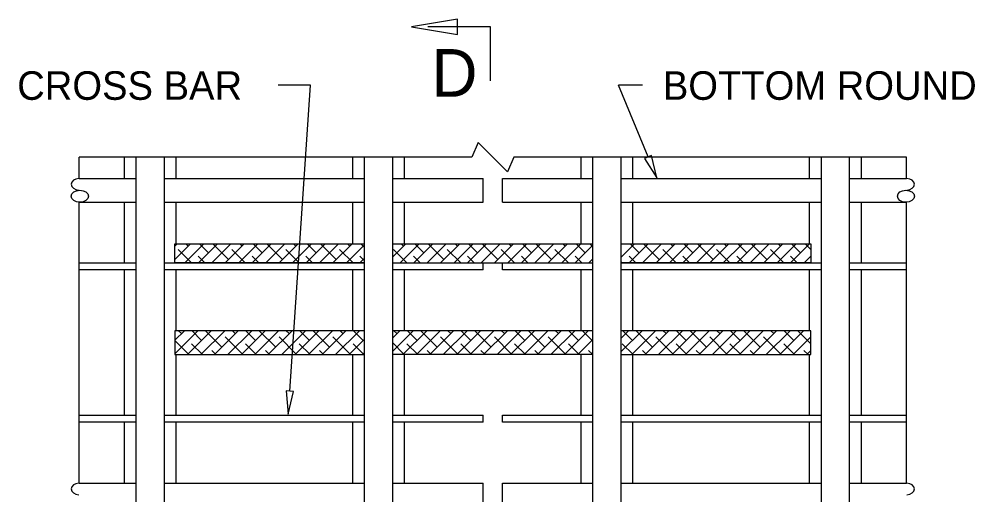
# Model space of a CAD drawing. Extents: x -24512 to -22484, y 4569 to 6351.
# Drawn here: x -24120.5 to -24020.1, y 5479 to 5529 of the extents above; entities that cross this region are included whole.
import ezdxf

# ---------------------------------------------------------------- set-up
doc = ezdxf.new("R2010")
doc.units = 0
for name, color, linetype in [('10', 7, 'Continuous'), ('3', 7, 'Continuous'), ('4', 7, 'Continuous'), ('8', 7, 'Continuous'), ('9', 7, 'Continuous')]:
    doc.layers.add(name, color=color, linetype=linetype)

# ---------------------------------------------------------------- blocks, each defined once
blk = doc.blocks.new('SYM048')
at = {"layer": '3'}
for p, q in [((150.97425, 287.263125), (151.306125, 287.595)), ((150.97425, 287.54825), (151.021, 287.595)), ((151.188, 287.19175), (151.59125, 287.595)), ((151.25775, 287.546625), (151.209375, 287.595)), ((151.473125, 287.19175), (151.876375, 287.595)), ((151.6855, 287.404), (151.4945, 287.595)), ((151.75825, 287.19175), (152.1615, 287.595)), ((152.113125, 287.2615), (151.779625, 287.595)), ((152.043375, 287.19175), (152.446625, 287.595)), ((152.3285, 287.19175), (152.73175, 287.595)), ((152.39825, 287.546625), (152.349875, 287.595)), ((152.613625, 287.19175), (153.016875, 287.595)), ((152.825875, 287.404), (152.635, 287.595)), ((152.89875, 287.19175), (153.302, 287.595)), ((153.253625, 287.2615), (152.920125, 287.595)), ((153.183875, 287.19175), (153.587125, 287.595)), ((153.469, 287.19175), (153.87225, 287.595)), ((153.53875, 287.546625), (153.490375, 287.595)), ((153.754125, 287.19175), (154.157375, 287.595)), ((153.966375, 287.404), (153.7755, 287.595)), ((154.03925, 287.19175), (154.4425, 287.595)), ((154.394125, 287.2615), (154.060625, 287.595)), ((154.324375, 287.19175), (154.727625, 287.595)), ((154.6095, 287.19175), (154.991375, 287.573625)), ((154.67925, 287.546625), (154.630875, 287.595)), ((154.991375, 287.519625), (154.916, 287.595)), ((151.3275, 287.19175), (151.043875, 287.475375)), ((151.612625, 287.19175), (151.471625, 287.33275)), ((152.468, 287.19175), (152.184375, 287.475375)), ((152.753125, 287.19175), (152.612125, 287.33275)), ((153.6085, 287.19175), (153.324875, 287.475375)), ((153.893625, 287.19175), (153.752625, 287.33275)), ((154.749, 287.19175), (154.465375, 287.475375)), ((154.991375, 287.2345), (154.893125, 287.33275)), ((154.894625, 287.19175), (154.991375, 287.2885))]:
    blk.add_line(p, q, dxfattribs=at)
blk = doc.blocks.new('SYM049')
at = {"layer": '3'}
for p, q in [((155.5905, 287.317375), (155.868125, 287.595)), ((155.75, 287.19175), (156.15325, 287.595)), ((155.81975, 287.546625), (155.771375, 287.595)), ((156.035125, 287.19175), (156.438375, 287.595)), ((156.247375, 287.404), (156.0565, 287.595)), ((156.32025, 287.19175), (156.7235, 287.595)), ((156.675125, 287.2615), (156.341625, 287.595)), ((156.605375, 287.19175), (157.0085, 287.595)), ((156.8905, 287.19175), (157.293625, 287.595)), ((156.96025, 287.546625), (156.911875, 287.595)), ((157.175625, 287.19175), (157.57875, 287.595)), ((157.387875, 287.404), (157.197, 287.595)), ((157.46075, 287.19175), (157.863875, 287.595)), ((157.815625, 287.2615), (157.482125, 287.595)), ((157.745875, 287.19175), (158.149, 287.595)), ((158.031, 287.19175), (158.434125, 287.595)), ((158.10075, 287.546625), (158.052375, 287.595)), ((158.316125, 287.19175), (158.71925, 287.595)), ((158.528375, 287.404), (158.3375, 287.595)), ((158.60125, 287.19175), (159.004375, 287.595)), ((158.956125, 287.2615), (158.622625, 287.595)), ((158.886375, 287.19175), (159.2895, 287.595)), ((159.1715, 287.19175), (159.574625, 287.595)), ((159.24125, 287.546625), (159.192875, 287.595)), ((159.456625, 287.19175), (159.83, 287.56525)), ((159.668875, 287.404), (159.478, 287.595)), ((159.83, 287.528), (159.763125, 287.595)), ((155.8895, 287.19175), (155.605875, 287.475375)), ((156.174625, 287.19175), (156.033625, 287.33275)), ((157.03, 287.19175), (156.746375, 287.475375)), ((157.315125, 287.19175), (157.174125, 287.33275)), ((158.1705, 287.19175), (157.886875, 287.475375)), ((158.455625, 287.19175), (158.3145, 287.33275)), ((159.311, 287.19175), (159.027375, 287.475375)), ((159.596125, 287.19175), (159.455, 287.33275)), ((159.74175, 287.19175), (159.83, 287.280125))]:
    blk.add_line(p, q, dxfattribs=at)
blk = doc.blocks.new('SYM050')
at = {"layer": '3'}
for p, q in [((160.42925, 287.309), (160.715125, 287.595)), ((160.42925, 287.594125), (160.43, 287.595)), ((160.597, 287.19175), (161.00025, 287.595)), ((160.809375, 287.404), (160.6185, 287.595)), ((160.882125, 287.19175), (161.285375, 287.595)), ((161.237125, 287.2615), (160.903625, 287.595)), ((161.16725, 287.19175), (161.5705, 287.595)), ((161.452375, 287.19175), (161.855625, 287.595)), ((161.52225, 287.546625), (161.473875, 287.595)), ((161.7375, 287.19175), (162.14075, 287.595)), ((161.949875, 287.404), (161.759, 287.595)), ((162.022625, 287.19175), (162.425875, 287.595)), ((162.3775, 287.2615), (162.044125, 287.595)), ((162.30775, 287.19175), (162.711, 287.595)), ((162.592875, 287.19175), (162.996125, 287.595)), ((162.662625, 287.546625), (162.614375, 287.595)), ((162.878, 287.19175), (163.28125, 287.595)), ((163.090375, 287.404), (162.8995, 287.595)), ((163.163125, 287.19175), (163.566375, 287.595)), ((163.518, 287.2615), (163.184625, 287.595)), ((163.44825, 287.19175), (163.8515, 287.595)), ((163.733375, 287.19175), (164.136625, 287.595)), ((163.803125, 287.546625), (163.754875, 287.595)), ((164.0185, 287.19175), (164.42175, 287.595)), ((164.230875, 287.404), (164.04, 287.595)), ((164.446375, 287.473625), (164.325125, 287.595)), ((160.736625, 287.19175), (160.5955, 287.33275)), ((161.592, 287.19175), (161.308375, 287.475375)), ((161.877125, 287.19175), (161.736, 287.33275)), ((162.7325, 287.19175), (162.448875, 287.475375)), ((163.017625, 287.19175), (162.8765, 287.33275)), ((163.873, 287.19175), (163.589375, 287.475375)), ((164.158, 287.19175), (164.017, 287.33275)), ((164.303625, 287.19175), (164.446375, 287.334375)), ((160.4515, 287.19175), (160.42925, 287.214))]:
    blk.add_line(p, q, dxfattribs=at)
blk = doc.blocks.new('SYM051')
at = {"layer": '3'}
for p, q in [((150.97425, 285.26725), (151.46225, 285.75525)), ((150.97425, 285.552375), (151.177125, 285.75525)), ((151.11525, 285.693375), (151.05325, 285.75525)), ((151.243375, 285.25125), (151.747375, 285.75525)), ((151.542875, 285.55075), (151.338375, 285.75525)), ((151.5285, 285.25125), (152.0325, 285.75525)), ((151.970625, 285.40825), (151.6235, 285.75525)), ((151.813625, 285.25125), (152.317625, 285.75525)), ((152.09875, 285.25125), (152.60275, 285.75525)), ((152.25575, 285.693375), (152.19375, 285.75525)), ((152.383875, 285.25125), (152.887875, 285.75525)), ((152.683375, 285.55075), (152.478875, 285.75525)), ((152.669, 285.25125), (153.173, 285.75525)), ((153.111, 285.40825), (152.764, 285.75525)), ((152.954125, 285.25125), (153.458125, 285.75525)), ((153.23925, 285.25125), (153.74325, 285.75525)), ((153.396125, 285.693375), (153.33425, 285.75525)), ((153.524375, 285.25125), (154.028375, 285.75525)), ((153.823875, 285.55075), (153.619375, 285.75525)), ((153.8095, 285.25125), (154.3135, 285.75525)), ((154.2515, 285.40825), (153.9045, 285.75525)), ((154.094625, 285.25125), (154.598625, 285.75525)), ((154.37975, 285.25125), (154.88375, 285.75525)), ((154.536625, 285.693375), (154.47475, 285.75525)), ((154.964375, 285.55075), (154.759875, 285.75525)), ((151.25775, 285.265625), (150.97425, 285.549125)), ((151.55725, 285.25125), (151.329, 285.4795)), ((152.39825, 285.265625), (152.041875, 285.622)), ((152.69775, 285.25125), (152.4695, 285.4795)), ((153.53875, 285.265625), (153.182375, 285.622)), ((153.83825, 285.25125), (153.61, 285.4795)), ((154.67925, 285.265625), (154.322875, 285.622)), ((154.664875, 285.25125), (154.991375, 285.57775)), ((154.97875, 285.25125), (154.7505, 285.4795)), ((151.842375, 285.25125), (151.75675, 285.336875)), ((152.982875, 285.25125), (152.89725, 285.336875)), ((154.123375, 285.25125), (154.03775, 285.336875)), ((154.95, 285.25125), (154.991375, 285.292625))]:
    blk.add_line(p, q, dxfattribs=at)
blk = doc.blocks.new('SYM052')
at = {"layer": '3'}
for p, q in [((155.5905, 285.321625), (156.02425, 285.75525)), ((155.5905, 285.606625), (155.739125, 285.75525)), ((155.677125, 285.693375), (155.61525, 285.75525)), ((155.80525, 285.25125), (156.309375, 285.75525)), ((156.104875, 285.55075), (155.900375, 285.75525)), ((156.090375, 285.25125), (156.5945, 285.75525)), ((156.5325, 285.40825), (156.1855, 285.75525)), ((156.3755, 285.25125), (156.879625, 285.75525)), ((156.660625, 285.25125), (157.16475, 285.75525)), ((156.817625, 285.693375), (156.75575, 285.75525)), ((156.94575, 285.25125), (157.449875, 285.75525)), ((157.245375, 285.55075), (157.040875, 285.75525)), ((157.230875, 285.25125), (157.735, 285.75525)), ((157.673, 285.40825), (157.326, 285.75525)), ((157.516, 285.25125), (158.020125, 285.75525)), ((157.801125, 285.25125), (158.30525, 285.75525)), ((157.958125, 285.693375), (157.89625, 285.75525)), ((158.08625, 285.25125), (158.590375, 285.75525)), ((158.385875, 285.55075), (158.181375, 285.75525)), ((158.371375, 285.25125), (158.8755, 285.75525)), ((158.8135, 285.40825), (158.4665, 285.75525)), ((158.6565, 285.25125), (159.160625, 285.75525)), ((158.941625, 285.25125), (159.44575, 285.75525)), ((159.098625, 285.693375), (159.03675, 285.75525)), ((159.22675, 285.25125), (159.730875, 285.75525)), ((159.526375, 285.55075), (159.321875, 285.75525)), ((159.83, 285.532125), (159.607, 285.75525)), ((155.81975, 285.265625), (155.5905, 285.494875)), ((156.11925, 285.25125), (155.891, 285.4795)), ((156.96025, 285.265625), (156.603875, 285.622)), ((157.25975, 285.25125), (157.0315, 285.4795)), ((158.10075, 285.265625), (157.74425, 285.622)), ((158.40025, 285.25125), (158.172, 285.4795)), ((159.24125, 285.265625), (158.88475, 285.622)), ((159.54075, 285.25125), (159.3125, 285.4795)), ((159.511875, 285.25125), (159.83, 285.569375)), ((156.404375, 285.25125), (156.31875, 285.336875)), ((157.544875, 285.25125), (157.459125, 285.336875)), ((158.685375, 285.25125), (158.599625, 285.336875)), ((159.825875, 285.25125), (159.740125, 285.336875)), ((159.797, 285.25125), (159.83, 285.28425))]:
    blk.add_line(p, q, dxfattribs=at)
blk = doc.blocks.new('SYM053')
at = {"layer": '3'}
for p, q in [((160.42925, 285.313125), (160.87125, 285.75525)), ((160.42925, 285.59825), (160.586125, 285.75525)), ((160.666875, 285.55075), (160.462375, 285.75525)), ((160.652375, 285.25125), (161.156375, 285.75525)), ((161.0945, 285.40825), (160.7475, 285.75525)), ((160.9375, 285.25125), (161.4415, 285.75525)), ((161.222625, 285.25125), (161.726625, 285.75525)), ((161.379625, 285.693375), (161.31775, 285.75525)), ((161.50775, 285.25125), (162.01175, 285.75525)), ((161.807375, 285.55075), (161.602875, 285.75525)), ((161.792875, 285.25125), (162.296875, 285.75525)), ((162.235, 285.40825), (161.888, 285.75525)), ((162.078, 285.25125), (162.582, 285.75525)), ((162.363125, 285.25125), (162.867125, 285.75525)), ((162.520125, 285.693375), (162.45825, 285.75525)), ((162.64825, 285.25125), (163.15225, 285.75525)), ((162.94775, 285.55075), (162.743375, 285.75525)), ((162.933375, 285.25125), (163.437375, 285.75525)), ((163.3755, 285.40825), (163.0285, 285.75525)), ((163.2185, 285.25125), (163.7225, 285.75525)), ((163.503625, 285.25125), (164.007625, 285.75525)), ((163.660625, 285.693375), (163.59875, 285.75525)), ((163.78875, 285.25125), (164.29275, 285.75525)), ((164.08825, 285.55075), (163.88375, 285.75525)), ((164.446375, 285.47775), (164.168875, 285.75525)), ((160.68125, 285.25125), (160.453, 285.4795)), ((161.52225, 285.265625), (161.16575, 285.622)), ((161.82175, 285.25125), (161.5935, 285.4795)), ((162.662625, 285.265625), (162.30625, 285.622)), ((162.96225, 285.25125), (162.734, 285.4795)), ((163.803125, 285.265625), (163.44675, 285.622)), ((164.10275, 285.25125), (163.8745, 285.4795)), ((164.073875, 285.25125), (164.446375, 285.62375)), ((160.966375, 285.25125), (160.880625, 285.336875)), ((162.106875, 285.25125), (162.021125, 285.336875)), ((163.247375, 285.25125), (163.161625, 285.336875)), ((164.387875, 285.25125), (164.302125, 285.336875)), ((164.359, 285.25125), (164.446375, 285.338625))]:
    blk.add_line(p, q, dxfattribs=at)

msp = doc.modelspace()

# ---------------------------------------------------------------- linework, layer by layer
at = {"layer": '10'}
for centre, major_axis, start_param, end_param in [((-24114.15, 5511.66), (0.895, 0), 1.692197, 4.591233), ((-24027.36, 5511.66), (-0.895, 0), 1.691952, 4.590988), ((-24114.15, 5479.66), (0.895, 0), 1.692197, 4.591233), ((-24027.36, 5479.66), (-0.895, 0), 1.691952, 4.590988)]:
    msp.add_ellipse(centre, major_axis=major_axis, ratio=0.699516, start_param=start_param, end_param=end_param, dxfattribs=at)
for centre, major_axis in [((-24114.15, 5510.41), (0.895, 0)), ((-24027.36, 5510.41), (-0.895, 0))]:
    msp.add_ellipse(centre, major_axis=major_axis, ratio=0.699516, dxfattribs=at)
at = {"layer": '3'}
msp.add_lwpolyline([(-24074.46, 5527.39), (-24074.46, 5529.01), (-24079.31, 5528.2)], close=True, dxfattribs=at)
msp.add_lwpolyline([(-24071, 5522.54), (-24071, 5528.2), (-24077.59, 5528.2)], dxfattribs=at)
at = {"layer": '4'}
for p, q in [((-24114.23, 5512.28), (-24114.23, 5514.51)), ((-24109.47, 5512.28), (-24109.47, 5514.51)), ((-24108.24, 5427.56), (-24108.24, 5514.51)), ((-24105.27, 5427.56), (-24105.27, 5514.51)), ((-24104.04, 5512.28), (-24104.04, 5514.51)), ((-24085.48, 5512.28), (-24085.48, 5514.51)), ((-24084.24, 5427.56), (-24084.24, 5514.51)), ((-24081.27, 5427.56), (-24081.27, 5514.51)), ((-24080.04, 5512.28), (-24080.04, 5514.51)), ((-24061.48, 5512.28), (-24061.48, 5514.51)), ((-24060.24, 5427.56), (-24060.24, 5514.51)), ((-24057.27, 5427.56), (-24057.27, 5514.51)), ((-24056.04, 5512.28), (-24056.04, 5514.51)), ((-24037.48, 5512.28), (-24037.48, 5514.51)), ((-24036.24, 5427.56), (-24036.24, 5514.51)), ((-24033.27, 5427.56), (-24033.27, 5514.51)), ((-24032.04, 5512.28), (-24032.04, 5514.51)), ((-24027.29, 5512.28), (-24027.29, 5514.51)), ((-24114.23, 5512.28), (-24108.24, 5512.28)), ((-24105.27, 5512.28), (-24084.24, 5512.28)), ((-24081.27, 5512.28), (-24071.76, 5512.28)), ((-24071.76, 5509.78), (-24071.76, 5512.28)), ((-24069.76, 5509.78), (-24069.76, 5512.28)), ((-24069.76, 5512.28), (-24060.24, 5512.28)), ((-24057.27, 5512.28), (-24036.24, 5512.28)), ((-24033.27, 5512.28), (-24027.29, 5512.28)), ((-24114.23, 5480.28), (-24114.23, 5509.78)), ((-24114.23, 5509.78), (-24108.24, 5509.78)), ((-24109.47, 5503.41), (-24109.47, 5509.78)), ((-24105.27, 5509.78), (-24084.24, 5509.78)), ((-24104.04, 5505.41), (-24104.04, 5509.78)), ((-24085.48, 5505.41), (-24085.48, 5509.78)), ((-24081.27, 5509.78), (-24071.76, 5509.78)), ((-24080.04, 5505.41), (-24080.04, 5509.78)), ((-24069.76, 5509.78), (-24060.24, 5509.78)), ((-24061.48, 5505.41), (-24061.48, 5509.78)), ((-24057.27, 5509.78), (-24036.24, 5509.78)), ((-24056.04, 5505.41), (-24056.04, 5509.78)), ((-24037.48, 5505.41), (-24037.48, 5509.78)), ((-24033.27, 5509.78), (-24027.29, 5509.78)), ((-24032.04, 5503.41), (-24032.04, 5509.78)), ((-24027.29, 5480.28), (-24027.29, 5509.78)), ((-24114.23, 5503.41), (-24108.24, 5503.41)), ((-24105.27, 5503.41), (-24084.24, 5503.41)), ((-24081.27, 5503.41), (-24071.76, 5503.41)), ((-24071.76, 5502.66), (-24071.76, 5503.41)), ((-24069.76, 5502.66), (-24069.76, 5503.41)), ((-24069.76, 5503.41), (-24060.24, 5503.41)), ((-24057.27, 5503.41), (-24036.24, 5503.41)), ((-24033.27, 5503.41), (-24027.29, 5503.41)), ((-24108.24, 5502.66), (-24114.23, 5502.66)), ((-24109.47, 5487.41), (-24109.47, 5502.66)), ((-24084.24, 5502.66), (-24105.27, 5502.66)), ((-24104.04, 5496.28), (-24104.04, 5502.66)), ((-24085.48, 5496.28), (-24085.48, 5502.66)), ((-24071.76, 5502.66), (-24081.27, 5502.66)), ((-24080.04, 5496.28), (-24080.04, 5502.66)), ((-24060.24, 5502.66), (-24069.76, 5502.66)), ((-24061.48, 5496.28), (-24061.48, 5502.66)), ((-24036.24, 5502.66), (-24057.27, 5502.66)), ((-24056.04, 5496.28), (-24056.04, 5502.66)), ((-24037.48, 5496.28), (-24037.48, 5502.66)), ((-24027.29, 5502.66), (-24033.27, 5502.66)), ((-24032.04, 5487.41), (-24032.04, 5502.66)), ((-24104.04, 5487.41), (-24104.04, 5493.78)), ((-24085.48, 5487.41), (-24085.48, 5493.78)), ((-24080.04, 5487.41), (-24080.04, 5493.78)), ((-24061.48, 5487.41), (-24061.48, 5493.78)), ((-24056.04, 5487.41), (-24056.04, 5493.78)), ((-24037.48, 5487.41), (-24037.48, 5493.78)), ((-24114.23, 5487.41), (-24108.24, 5487.41)), ((-24105.27, 5487.41), (-24084.24, 5487.41)), ((-24081.27, 5487.41), (-24071.76, 5487.41)), ((-24071.76, 5486.66), (-24071.76, 5487.41)), ((-24069.76, 5486.66), (-24069.76, 5487.41)), ((-24069.76, 5487.41), (-24060.24, 5487.41)), ((-24057.27, 5487.41), (-24036.24, 5487.41)), ((-24033.27, 5487.41), (-24027.29, 5487.41)), ((-24108.24, 5486.66), (-24114.23, 5486.66)), ((-24109.47, 5480.28), (-24109.47, 5486.66)), ((-24084.24, 5486.66), (-24105.27, 5486.66)), ((-24104.04, 5480.28), (-24104.04, 5486.66)), ((-24085.48, 5480.28), (-24085.48, 5486.66)), ((-24071.76, 5486.66), (-24081.27, 5486.66)), ((-24080.04, 5480.28), (-24080.04, 5486.66)), ((-24060.24, 5486.66), (-24069.76, 5486.66)), ((-24061.48, 5480.28), (-24061.48, 5486.66)), ((-24036.24, 5486.66), (-24057.27, 5486.66)), ((-24056.04, 5480.28), (-24056.04, 5486.66)), ((-24037.48, 5480.28), (-24037.48, 5486.66)), ((-24027.29, 5486.66), (-24033.27, 5486.66)), ((-24032.04, 5480.28), (-24032.04, 5486.66)), ((-24114.23, 5480.28), (-24108.24, 5480.28)), ((-24105.27, 5480.28), (-24084.24, 5480.28)), ((-24081.27, 5480.28), (-24071.76, 5480.28)), ((-24071.76, 5477.78), (-24071.76, 5480.28)), ((-24069.76, 5477.78), (-24069.76, 5480.28)), ((-24069.76, 5480.28), (-24060.24, 5480.28)), ((-24057.27, 5480.28), (-24036.24, 5480.28)), ((-24033.27, 5480.28), (-24027.29, 5480.28))]:
    msp.add_line(p, q, dxfattribs=at)
msp.add_lwpolyline([(-24027.29, 5514.51), (-24068.56, 5514.51), (-24069.21, 5512.95), (-24072.31, 5516.06), (-24072.95, 5514.51), (-24114.23, 5514.51)], dxfattribs=at)
at = {"layer": '8'}
for p, q in [((-24081.27, 5505.41), (-24060.24, 5505.41)), ((-24081.27, 5503.41), (-24060.24, 5503.41)), ((-24060.24, 5496.28), (-24081.27, 5496.28)), ((-24060.24, 5493.78), (-24081.27, 5493.78))]:
    msp.add_line(p, q, dxfattribs=at)
for points in [[(-24084.24, 5503.41), (-24104.17, 5503.41), (-24104.17, 5505.41), (-24084.24, 5505.41)], [(-24057.27, 5505.41), (-24037.35, 5505.41), (-24037.35, 5503.41), (-24057.27, 5503.41)], [(-24084.24, 5496.28), (-24104.17, 5496.28), (-24104.17, 5493.78), (-24084.24, 5493.78)], [(-24057.27, 5493.78), (-24037.35, 5493.78), (-24037.35, 5496.28), (-24057.27, 5496.28)]]:
    msp.add_lwpolyline(points, dxfattribs=at)
at = {"layer": '9'}
for p, q in [((-24090.36, 5522.08), (-24093.33, 5522.08)), ((-24089.9, 5522.08), (-24092.76, 5522.08)), ((-24092.08, 5489.93), (-24089.9, 5522.08)), ((-24054.45, 5514.54), (-24057.55, 5522.08)), ((-24055.05, 5522.08), (-24057.55, 5522.08))]:
    msp.add_line(p, q, dxfattribs=at)
for points in [[(-24054.08, 5514.69), (-24054.82, 5514.38), (-24053.54, 5512.32)], [(-24091.69, 5489.9), (-24092.48, 5489.95), (-24092.25, 5487.53)]]:
    msp.add_lwpolyline(points, close=True, dxfattribs=at)

# ---------------------------------------------------------------- block references
at = {"layer": '3', "xscale": 4.95984251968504, "yscale": 4.95984251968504}
for name in ['SYM048', 'SYM049', 'SYM050', 'SYM051', 'SYM052', 'SYM053']:
    msp.add_blockref(name, (-24852.98, 4078.98), dxfattribs=at)

# ---------------------------------------------------------------- texts
at = {"layer": '9'}
for s, height, p in [('D', 5, (-24077.2, 5520.86)), ('CROSS BAR', 3, (-24120.73, 5520.53)), ('BOTTOM ROUND', 2.9999, (-24052.9, 5520.53))]:
    msp.add_text(s, height=height, dxfattribs=at).set_placement(p)

doc.saveas('drawing.dxf')
